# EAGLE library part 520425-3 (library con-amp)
AMP connector
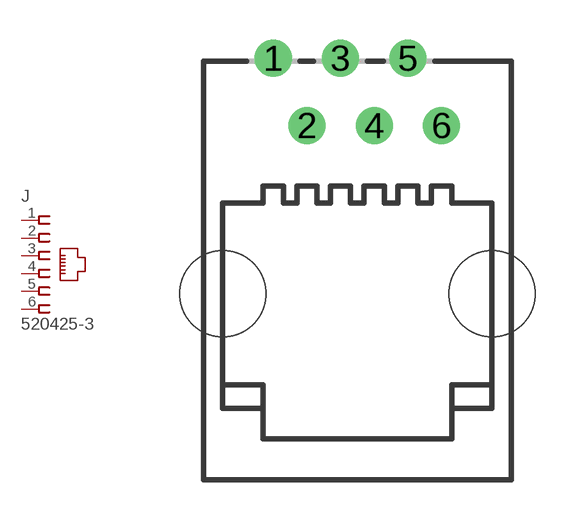
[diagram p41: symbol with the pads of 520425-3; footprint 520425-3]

Designator prefix J

## 520425-3 (MF: TYCO ELECTRONICS; MPN: 5520425-3; OC_FARNELL: 1773036; OC_NEWARK: 42K7231)  [520425-3]
1  1  pas
2  2  pas
3  3  pas
4  4  pas
5  5  pas
6  6  pas

## Footprint 520425-3 (pad centres in mm)
Modular Jack without Panel Stops
drill 0.889 round: 1 -3.175,8.001; 2 -1.905,5.461; 3 -0.635,8.001; 4 0.635,5.461; 5 1.905,8.001; 6 3.175,5.461
hole 3.251 at -5.08,-0.889
hole 3.251 at 5.08,-0.889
